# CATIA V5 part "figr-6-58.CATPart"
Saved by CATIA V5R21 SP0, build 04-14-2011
Part number: Part1
Bounding box of the stored display mesh (mm): x -50.648 to 50.648, y -72.183 to 72.183, z -40 to 40
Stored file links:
  D:\CATIA V5R21 E-RESOURCES\CATIA-V5R21\catia-v5r21-prt\c06-catia-v5r21-prt\c06-catia-v5r21-figr-6-58.CATPart
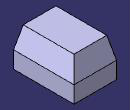
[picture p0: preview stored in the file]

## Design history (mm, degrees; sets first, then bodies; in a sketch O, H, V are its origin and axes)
Body1 (main body)
  Sketch1 on xy-plane, origin (0, 0, 0), H (1, 0, 0), V (0, 1, 0)
    line L1 (-50.6478, 72.1832) -> (50.6478, 72.1832)
    line L2 (50.6478, 72.1832) -> (50.6478, -72.1832)
    line L3 (50.6478, -72.1832) -> (-50.6478, -72.1832)
    line L4 (-50.6478, -72.1832) -> (-50.6478, 72.1832)
    axis line L5 (50.6478, -72.1832) -> (-50.6478, 72.1832)
    horizontal: L1 H, L3 H
    vertical: L2 V, L4 V
    midpoint: O L5
  Pad1: profile Sketch1, direction (0, 0, 1), length 40, mirrored extent
  Draft1: Angle 30, Neutral xy-plane, PullDir (0, 0, 1), SupportToDraft (face of Pad1; face of Pad1)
